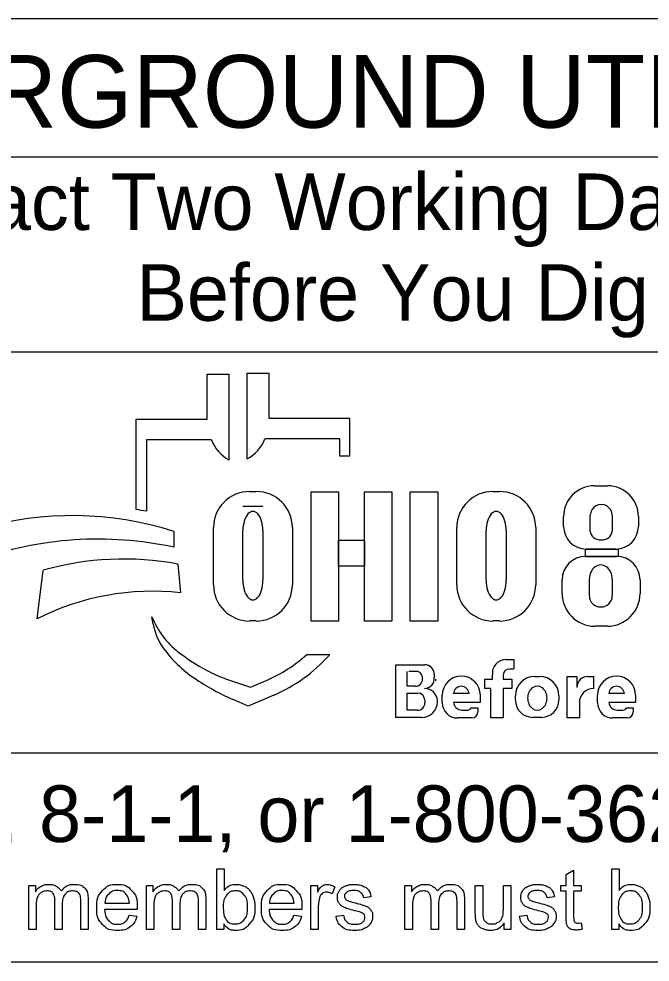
# Model space of a CAD drawing. Extents: x 0 to 34, y 0 to 22.
# Drawn here: x 26.673 to 28.237, y 9.069 to 11.406 of the extents above; entities that cross this region are included whole.
import ezdxf

# ---------------------------------------------------------------- set-up
doc = ezdxf.new("R2010")
doc.units = 0
doc.layers.add('SH_Data', color=7, linetype='Continuous')
doc.layers.add('SH_Text', color=7, linetype='Continuous')

msp = doc.modelspace()

# ---------------------------------------------------------------- linework, layer by layer
at = {"layer": 'SH_Data'}
for p, q in [((30.0333, 11.4064), (25.7833, 11.4064)), ((25.7833, 11.0648), (30.0333, 11.0648)), ((25.7833, 10.5814), (30.0333, 10.5814)), ((30.0333, 9.5868), (25.7833, 9.5868)), ((30.0333, 9.0689), (25.7833, 9.0689))]:
    msp.add_line(p, q, dxfattribs=at)
at = {"layer": 'SH_Text'}
for p, q in [((27.1394, 10.4144), (27.1394, 10.5259)), ((27.1394, 10.5259), (27.193, 10.5259)), ((27.193, 10.5259), (27.193, 10.3138)), ((27.2387, 10.3161), (27.2387, 10.5282)), ((27.2387, 10.5282), (27.2923, 10.5282)), ((27.2923, 10.5282), (27.2923, 10.4167)), ((26.9634, 10.1905), (26.9634, 10.4144)), ((26.9634, 10.4144), (27.1394, 10.4144)), ((27.2923, 10.4167), (27.4916, 10.4167)), ((27.4916, 10.4167), (27.4916, 10.3229)), ((26.9887, 10.363), (26.9887, 10.1861)), ((27.1498, 10.363), (26.9887, 10.363)), ((27.4683, 10.3653), (27.2819, 10.3653)), ((27.4683, 10.3229), (27.4683, 10.3653)), ((27.4916, 10.3229), (27.4683, 10.3229)), ((28.0989, 10.2492), (28.1317, 10.2492)), ((27.2444, 10.2352), (27.2609, 10.2352)), ((27.8474, 10.2352), (27.8639, 10.2352)), ((27.2776, 10.1982), (27.2278, 10.1982)), ((28.0226, 10.1486), (28.0226, 10.1729)), ((28.0888, 10.1372), (28.0888, 10.1765)), ((28.1429, 10.1765), (28.1429, 10.1372)), ((28.208, 10.1729), (28.208, 10.1486)), ((27.1549, 10.0037), (27.1549, 10.1457)), ((27.3504, 10.1457), (27.3504, 10.0037)), ((27.7579, 10.0037), (27.7579, 10.1457)), ((27.9534, 10.1457), (27.9534, 10.0037)), ((27.0567, 10.1358), (27.0567, 10.097)), ((27.2278, 10.0151), (27.2278, 10.1375)), ((27.2776, 10.1375), (27.2776, 10.0151)), ((27.8308, 10.0151), (27.8308, 10.1375)), ((27.8806, 10.1375), (27.8806, 10.0151)), ((28.152, 10.0926), (28.0786, 10.0926)), ((27.0667, 10.0552), (27.0729, 9.9843)), ((28.0768, 10.0743), (28.1541, 10.0743)), ((26.7179, 9.9197), (26.7326, 10.0398)), ((28.0189, 9.9824), (28.0189, 10.0164)), ((28.0864, 9.9764), (28.0864, 10.0173)), ((28.1433, 10.0173), (28.1433, 9.9764)), ((28.212, 10.0164), (28.212, 9.9824)), ((27.0056, 9.9068), (27.0025, 9.9247)), ((27.2609, 9.9143), (27.2444, 9.9143)), ((27.8639, 9.9143), (27.8474, 9.9143)), ((28.1311, 9.9014), (28.0999, 9.9014)), ((27.3859, 9.8309), (27.4433, 9.8309)), ((27.8797, 9.8187), (27.8992, 9.8187)), ((27.8992, 9.8187), (27.8992, 9.7957)), ((27.6072, 9.6751), (27.6072, 9.8059)), ((27.6072, 9.8059), (27.6783, 9.8059)), ((27.8992, 9.7952), (27.889, 9.7952)), ((27.6351, 9.7524), (27.6351, 9.7893)), ((27.6603, 9.7893), (27.6391, 9.7893)), ((27.7021, 9.7821), (27.7021, 9.7742)), ((27.8465, 9.7703), (27.8465, 9.7807)), ((27.8726, 9.7787), (27.8726, 9.7703)), ((27.951, 9.7769), (27.9631, 9.7769)), ((28.0312, 9.6739), (28.0312, 9.7766)), ((28.0312, 9.7766), (28.0558, 9.7766)), ((28.0558, 9.7766), (28.0558, 9.7498)), ((28.083, 9.7766), (28.0969, 9.7766)), ((28.0969, 9.7766), (28.0969, 9.747)), ((27.1874, 9.7705), (27.2469, 9.75)), ((27.2469, 9.75), (27.2879, 9.7678)), ((27.6545, 9.7524), (27.6351, 9.7524)), ((27.8271, 9.7473), (27.8271, 9.7703)), ((27.8271, 9.7703), (27.8465, 9.7703)), ((27.8726, 9.7703), (27.8941, 9.7703)), ((27.8941, 9.7703), (27.8941, 9.7473)), ((27.3041, 9.7305), (27.2408, 9.703)), ((27.6351, 9.693), (27.6351, 9.7358)), ((27.6351, 9.7358), (27.6607, 9.7358)), ((27.7217, 9.7119), (27.7217, 9.7303)), ((27.7883, 9.7343), (27.7498, 9.7343)), ((27.8162, 9.7303), (27.8162, 9.7127)), ((27.842, 9.7473), (27.8271, 9.7473)), ((27.842, 9.6739), (27.842, 9.7473)), ((27.8941, 9.7473), (27.8726, 9.7473)), ((27.8726, 9.7473), (27.8726, 9.6739)), ((27.9031, 9.7183), (27.9031, 9.729)), ((28.0109, 9.729), (28.0109, 9.7183)), ((28.1066, 9.7119), (28.1066, 9.7303)), ((28.1732, 9.7343), (28.1347, 9.7343)), ((28.2011, 9.7303), (28.2011, 9.7127)), ((27.2408, 9.703), (27.2035, 9.7195)), ((27.6788, 9.7177), (27.6788, 9.7114)), ((27.7101, 9.7148), (27.7101, 9.7145)), ((27.8162, 9.7127), (27.7498, 9.7127)), ((28.0617, 9.7121), (28.0617, 9.6739)), ((28.2011, 9.7127), (28.1347, 9.7127)), ((27.6604, 9.693), (27.6351, 9.693)), ((27.7707, 9.6934), (27.7849, 9.6934)), ((27.7934, 9.699), (27.8103, 9.699)), ((27.8103, 9.699), (27.8103, 9.6892)), ((28.1557, 9.6934), (28.1698, 9.6934)), ((28.1783, 9.699), (28.1952, 9.699)), ((28.1952, 9.699), (28.1952, 9.6892)), ((27.6708, 9.6751), (27.6072, 9.6751)), ((27.7951, 9.6739), (27.7597, 9.6739)), ((27.8726, 9.6739), (27.842, 9.6739)), ((27.9681, 9.6755), (27.9459, 9.6755)), ((28.0617, 9.6739), (28.0312, 9.6739)), ((28.18, 9.6739), (28.1446, 9.6739))]:
    msp.add_line(p, q, dxfattribs=at)
for points in [[(27.3968, 10.2342), (27.4648, 10.2342), (27.4648, 9.9142), (27.3968, 9.9142)], [(27.5289, 10.2342), (27.5969, 10.2342), (27.5969, 9.9142), (27.5289, 9.9142)], [(27.6423, 10.2342), (27.711, 10.2342), (27.711, 9.9142), (27.6423, 9.9142)], [(27.4648, 10.1143), (27.5289, 10.1143), (27.5289, 10.0503), (27.4648, 10.0503)], [(28.0765, 10.0926), (28.1582, 10.0926), (28.1582, 10.0742), (28.0765, 10.0742)]]:
    msp.add_lwpolyline(points, close=True, dxfattribs=at)
for points in [[(27.1802, 9.15), (27.1631, 9.15), (27.1631, 9.3002), (27.1815, 9.3002), (27.1815, 9.2467)], [(28.0291, 9.1819), (28.0291, 9.2446), (28.0155, 9.2446), (28.0155, 9.2589), (28.0291, 9.2589), (28.0291, 9.2858), (28.0475, 9.2969), (28.0475, 9.2589), (28.066, 9.2589), (28.066, 9.2446), (28.0475, 9.2446), (28.0475, 9.1808)], [(28.1592, 9.15), (28.1422, 9.15), (28.1422, 9.3002), (28.1606, 9.3002), (28.1606, 9.2467)], [(26.6971, 9.15), (26.6971, 9.2589), (26.7136, 9.2589), (26.7136, 9.2435)], [(26.9885, 9.15), (26.9885, 9.2589), (27.0049, 9.2589), (27.0049, 9.2435)], [(27.3962, 9.15), (27.3962, 9.2589), (27.4128, 9.2589), (27.4128, 9.2424)], [(27.6294, 9.15), (27.6294, 9.2589), (27.6459, 9.2589), (27.6459, 9.2435)], [(27.8038, 9.1915), (27.8038, 9.2589), (27.8222, 9.2589), (27.8222, 9.1985)], [(27.8735, 9.2006), (27.8735, 9.2589), (27.8919, 9.2589), (27.8919, 9.15), (27.8754, 9.15)], [(27.4553, 9.2554), (27.4488, 9.2383)], [(26.7802, 9.2132), (26.7802, 9.15), (26.7617, 9.15), (26.7617, 9.2207)], [(26.8446, 9.2247), (26.8446, 9.15), (26.8262, 9.15), (26.8262, 9.2185)], [(26.8857, 9.2148), (26.9465, 9.2148)], [(27.0715, 9.2132), (27.0715, 9.15), (27.0531, 9.15), (27.0531, 9.2207)], [(27.136, 9.2247), (27.136, 9.15), (27.1175, 9.15), (27.1175, 9.2185)], [(27.2937, 9.2148), (27.3545, 9.2148)], [(27.5452, 9.2307), (27.5272, 9.2283)], [(27.7125, 9.2132), (27.7125, 9.15), (27.6941, 9.15), (27.6941, 9.2207)], [(27.777, 9.2247), (27.777, 9.15), (27.7585, 9.15), (27.7585, 9.2185)], [(27.9998, 9.2307), (27.9817, 9.2283)], [(26.7155, 9.2064), (26.7155, 9.15), (26.6971, 9.15)], [(26.9658, 9.1997), (26.8847, 9.1997)], [(27.0069, 9.2064), (27.0069, 9.15), (26.9885, 9.15)], [(27.3738, 9.1997), (27.2927, 9.1997)], [(27.4147, 9.207), (27.4147, 9.15), (27.3962, 9.15)], [(27.6479, 9.2064), (27.6479, 9.15), (27.6294, 9.15)], [(26.9463, 9.1852), (26.9653, 9.1828)], [(27.1802, 9.1636), (27.1802, 9.15)], [(27.3543, 9.1852), (27.3733, 9.1828)], [(27.4588, 9.1825), (27.477, 9.1854)], [(27.8754, 9.15), (27.8754, 9.1661)], [(27.9134, 9.1825), (27.9316, 9.1854)], [(28.066, 9.1665), (28.0686, 9.1502)], [(28.1592, 9.1636), (28.1592, 9.15)]]:
    msp.add_lwpolyline(points, dxfattribs=at)
for centre, radius, start, end in [((27.2411, 10.3997), 0.0985, 201.9296, 240.7469), ((27.1906, 10.4021), 0.0985, 299.2531, 338.0704), ((28.0989, 10.1729), 0.0763, 90, 180), ((28.1317, 10.1729), 0.0763, 0, 90), ((27.2444, 10.1457), 0.0895, 90, 180), ((27.2609, 10.1457), 0.0895, 0, 90), ((27.8474, 10.1457), 0.0895, 90, 180), ((27.8639, 10.1457), 0.0895, 0, 90), ((26.8055, 9.3563), 0.8191, 72.1402, 106.3144), ((26.8353, 9.3815), 0.8191, 79.2074, 81.0007), ((28.0786, 10.1486), 0.056, 180, 270), ((28.152, 10.1486), 0.056, 270, 0), ((26.8686, 9.2252), 0.8919, 77.8238, 109.8274), ((26.9325, 9.3355), 0.7322, 79.44, 105.8467), ((28.0768, 10.0164), 0.0579, 90, 180), ((28.1541, 10.0164), 0.0579, 0, 90), ((27.0045, 9.3523), 0.6357, 83.8248, 116.8021), ((27.2444, 10.0037), 0.0895, 180, 270), ((27.2609, 10.0037), 0.0895, 270, 0), ((27.8474, 10.0037), 0.0895, 180, 270), ((27.8639, 10.0037), 0.0895, 270, 0), ((28.0999, 9.9824), 0.081, 180, 270), ((28.1311, 9.9824), 0.081, 270, 0), ((27.1899, 9.9968), 0.2008, 201.0457, 232.5314), ((27.1469, 9.9309), 0.1433, 189.6817, 216.0884), ((27.2805, 10.0283), 0.3088, 216.0884, 235.7167), ((27.3824, 10.248), 0.5173, 232.5314, 241.794), ((27.1445, 10.0983), 0.3602, 293.4582, 312.0712), ((27.1445, 10.0983), 0.401, 293.4582, 317.8286), ((27.8797, 9.7851), 0.0335, 90, 187.5187), ((27.6783, 9.7821), 0.0238, 0, 90), ((27.889, 9.7787), 0.0165, 90, 180), ((27.4471, 10.2726), 0.6044, 235.7167, 246.2325), ((27.2973, 10.0892), 0.3371, 241.794, 250.9821), ((27.6545, 9.7711), 0.0187, 270, 2.0582), ((27.6564, 9.7724), 0.0169, 357.8325, 90), ((27.6779, 9.7714), 0.0243, 270, 6.6529), ((27.769, 9.7303), 0.0473, 0, 180), ((27.951, 9.729), 0.0478, 90, 180), ((27.9631, 9.729), 0.0478, 0, 90), ((28.0826, 9.7498), 0.0269, 89.2449, 180), ((28.1539, 9.7303), 0.0473, 0, 180), ((27.6885, 9.7699), 0.0175, 347.4023, 0), ((27.769, 9.7333), 0.0193, 2.9632, 177.0368), ((28.1539, 9.7333), 0.0193, 2.9632, 177.0368), ((27.6607, 9.7177), 0.0181, 0, 90), ((27.678, 9.715), 0.0321, 4.0748, 90), ((28.0966, 9.7121), 0.0349, 89.6033, 180), ((27.6604, 9.7114), 0.0184, 270, 0), ((27.6708, 9.7145), 0.0393, 270, 0), ((27.6772, 9.7148), 0.033, 0, 11.7502), ((27.7597, 9.7119), 0.038, 180, 270), ((27.7707, 9.7144), 0.021, 184.827, 270), ((27.9459, 9.7183), 0.0428, 180, 270), ((27.9681, 9.7183), 0.0428, 270, 0), ((28.1446, 9.7119), 0.038, 180, 270), ((28.1557, 9.7144), 0.021, 184.827, 270), ((27.7849, 9.7028), 0.00938, 270, 335.9979), ((27.7951, 9.6892), 0.0152, 270, 0), ((28.1698, 9.7028), 0.00938, 270, 335.9979), ((28.18, 9.6892), 0.0152, 270, 0)]:
    msp.add_arc(centre, radius, start, end, dxfattribs=at)
for centre, major_axis, ratio, start_param, end_param in [((28.1159, 10.1765), (0.0271, 0), 0.969373, 0, 3.141593), ((27.2527, 10.1375), (0, 0.0484), 0.514403, 4.712389, 7.853982), ((27.8557, 10.1375), (0, 0.0484), 0.514403, 4.712389, 7.853982), ((28.1159, 10.1372), (0.0271, 0), 0.818453, 3.141593, 6.283185), ((28.1148, 10.0173), (0, 0.0358), 0.794529, 4.712389, 7.853982), ((27.2527, 10.0151), (0, 0.0484), 0.514403, 1.570796, 4.712389), ((27.8557, 10.0151), (0, 0.0484), 0.514403, 1.570796, 4.712389), ((28.1148, 9.9764), (0.0284, 0), 0.959837, 3.141593, 6.283185), ((27.9575, 9.7236), (0, 0.029), 0.832186, 4.712389, 7.853982), ((27.9575, 9.7236), (0, 0.0302), 0.797287, 1.570796, 4.712389)]:
    msp.add_ellipse(centre, major_axis=major_axis, ratio=ratio, start_param=start_param, end_param=end_param, dxfattribs=at)
for points in [[(26.7136, 9.2435), (26.7187, 9.2515), (26.7272, 9.2564), (26.7357, 9.2613), (26.7466, 9.2613), (26.7586, 9.2613), (26.7664, 9.2562), (26.7741, 9.2512), (26.7773, 9.2422), (26.7902, 9.2613), (26.8109, 9.2613), (26.8272, 9.2613), (26.8359, 9.2523), (26.8446, 9.2433), (26.8446, 9.2247)], [(26.9653, 9.1828), (26.9608, 9.1661), (26.9486, 9.1568), (26.9364, 9.1476), (26.9175, 9.1476), (26.8936, 9.1476), (26.8797, 9.1623), (26.8657, 9.177), (26.8657, 9.2035), (26.8657, 9.231), (26.8798, 9.2461), (26.8939, 9.2613), (26.9165, 9.2613), (26.9383, 9.2613), (26.9521, 9.2464), (26.9659, 9.2316), (26.9659, 9.2046), (26.9659, 9.203), (26.9658, 9.1997)], [(27.0049, 9.2435), (27.0101, 9.2515), (27.0186, 9.2564), (27.0271, 9.2613), (27.0379, 9.2613), (27.05, 9.2613), (27.0578, 9.2562), (27.0655, 9.2512), (27.0687, 9.2422), (27.0816, 9.2613), (27.1023, 9.2613), (27.1185, 9.2613), (27.1272, 9.2523), (27.136, 9.2433), (27.136, 9.2247)], [(27.1815, 9.2467), (27.1932, 9.2613), (27.2113, 9.2613), (27.2214, 9.2613), (27.2303, 9.2572), (27.2393, 9.2532), (27.2451, 9.2459), (27.2509, 9.2385), (27.2541, 9.2282), (27.2574, 9.2179), (27.2574, 9.2061), (27.2574, 9.1781), (27.2436, 9.1629), (27.2298, 9.1476), (27.2104, 9.1476), (27.1911, 9.1476), (27.1802, 9.1636)], [(27.3733, 9.1828), (27.3688, 9.1661), (27.3566, 9.1568), (27.3444, 9.1476), (27.3255, 9.1476), (27.3016, 9.1476), (27.2876, 9.1623), (27.2737, 9.177), (27.2737, 9.2035), (27.2737, 9.231), (27.2878, 9.2461), (27.3019, 9.2613), (27.3245, 9.2613), (27.3463, 9.2613), (27.3601, 9.2464), (27.3739, 9.2316), (27.3739, 9.2046), (27.3739, 9.203), (27.3738, 9.1997)], [(27.4128, 9.2424), (27.4192, 9.2539), (27.4245, 9.2576), (27.4299, 9.2613), (27.4364, 9.2613), (27.4457, 9.2613), (27.4553, 9.2554)], [(27.477, 9.1854), (27.4786, 9.1744), (27.4856, 9.1686), (27.4927, 9.1627), (27.5053, 9.1627), (27.518, 9.1627), (27.5242, 9.1679), (27.5304, 9.1731), (27.5304, 9.1801), (27.5304, 9.1863), (27.5249, 9.1899), (27.5211, 9.1924), (27.506, 9.1962), (27.4857, 9.2013), (27.4779, 9.205), (27.47, 9.2088), (27.466, 9.2154), (27.4619, 9.222), (27.4619, 9.2299), (27.4619, 9.2372), (27.4653, 9.2434), (27.4686, 9.2496), (27.4743, 9.2537), (27.4786, 9.2569), (27.4861, 9.2591), (27.4935, 9.2613), (27.502, 9.2613), (27.5149, 9.2613), (27.5246, 9.2576), (27.5343, 9.2539), (27.5389, 9.2476), (27.5435, 9.2413), (27.5452, 9.2307)], [(27.6459, 9.2435), (27.6511, 9.2515), (27.6596, 9.2564), (27.6681, 9.2613), (27.6789, 9.2613), (27.691, 9.2613), (27.6988, 9.2562), (27.7065, 9.2512), (27.7097, 9.2422), (27.7226, 9.2613), (27.7433, 9.2613), (27.7595, 9.2613), (27.7682, 9.2523), (27.777, 9.2433), (27.777, 9.2247)], [(27.9316, 9.1854), (27.9331, 9.1744), (27.9402, 9.1686), (27.9472, 9.1627), (27.9599, 9.1627), (27.9726, 9.1627), (27.9788, 9.1679), (27.9849, 9.1731), (27.9849, 9.1801), (27.9849, 9.1863), (27.9795, 9.1899), (27.9757, 9.1924), (27.9606, 9.1962), (27.9403, 9.2013), (27.9324, 9.205), (27.9246, 9.2088), (27.9205, 9.2154), (27.9165, 9.222), (27.9165, 9.2299), (27.9165, 9.2372), (27.9198, 9.2434), (27.9232, 9.2496), (27.9289, 9.2537), (27.9332, 9.2569), (27.9407, 9.2591), (27.9481, 9.2613), (27.9566, 9.2613), (27.9694, 9.2613), (27.9791, 9.2576), (27.9888, 9.2539), (27.9934, 9.2476), (27.9981, 9.2413), (27.9998, 9.2307)], [(28.1606, 9.2467), (28.1723, 9.2613), (28.1904, 9.2613), (28.2004, 9.2613), (28.2094, 9.2572), (28.2184, 9.2532), (28.2241, 9.2459), (28.2299, 9.2385), (28.2332, 9.2282), (28.2365, 9.2179), (28.2365, 9.2061), (28.2365, 9.1781), (28.2226, 9.1629), (28.2088, 9.1476), (28.1895, 9.1476), (28.1702, 9.1476), (28.1592, 9.1636)], [(26.7617, 9.2207), (26.7617, 9.233), (26.7572, 9.2391), (26.7527, 9.2452), (26.7425, 9.2452), (26.7347, 9.2452), (26.7281, 9.2411), (26.7214, 9.2371), (26.7185, 9.2292), (26.7155, 9.2213), (26.7155, 9.2064)], [(26.8262, 9.2185), (26.8262, 9.2296), (26.8244, 9.2344), (26.8226, 9.2393), (26.8179, 9.2423), (26.8132, 9.2452), (26.8068, 9.2452), (26.7953, 9.2452), (26.7877, 9.2376), (26.7802, 9.23), (26.7802, 9.2132)], [(26.9465, 9.2148), (26.9452, 9.2286), (26.9395, 9.2355), (26.9307, 9.2462), (26.9166, 9.2462), (26.9039, 9.2462), (26.8953, 9.2376), (26.8866, 9.2291), (26.8857, 9.2148)], [(27.0531, 9.2207), (27.0531, 9.233), (27.0486, 9.2391), (27.0441, 9.2452), (27.0338, 9.2452), (27.026, 9.2452), (27.0194, 9.2411), (27.0128, 9.2371), (27.0098, 9.2292), (27.0069, 9.2213), (27.0069, 9.2064)], [(27.1175, 9.2185), (27.1175, 9.2296), (27.1157, 9.2344), (27.114, 9.2393), (27.1092, 9.2423), (27.1045, 9.2452), (27.0982, 9.2452), (27.0867, 9.2452), (27.0791, 9.2376), (27.0715, 9.23), (27.0715, 9.2132)], [(27.1799, 9.2053), (27.1799, 9.1857), (27.1853, 9.177), (27.1939, 9.1627), (27.2088, 9.1627), (27.2208, 9.1627), (27.2296, 9.1732), (27.2384, 9.1837), (27.2384, 9.2045), (27.2384, 9.2259), (27.23, 9.236), (27.2215, 9.2462), (27.2096, 9.2462), (27.1975, 9.2462), (27.1887, 9.2357), (27.1799, 9.2251), (27.1799, 9.2053)], [(27.3545, 9.2148), (27.3532, 9.2286), (27.3475, 9.2355), (27.3387, 9.2462), (27.3246, 9.2462), (27.3119, 9.2462), (27.3033, 9.2376), (27.2946, 9.2291), (27.2937, 9.2148)], [(27.4488, 9.2383), (27.4421, 9.2423), (27.4354, 9.2423), (27.4294, 9.2423), (27.4246, 9.2386), (27.4198, 9.235), (27.4177, 9.2285), (27.4147, 9.2187), (27.4147, 9.207)], [(27.5272, 9.2283), (27.5259, 9.2367), (27.52, 9.2414), (27.5141, 9.2462), (27.5034, 9.2462), (27.4906, 9.2462), (27.4852, 9.2419), (27.4798, 9.2377), (27.4798, 9.2321), (27.4798, 9.2285), (27.482, 9.2256), (27.4843, 9.2227), (27.4891, 9.2207), (27.4919, 9.2197), (27.5054, 9.216), (27.525, 9.2108), (27.5328, 9.2074), (27.5405, 9.2041), (27.5449, 9.1978), (27.5494, 9.1914), (27.5494, 9.182), (27.5494, 9.1728), (27.544, 9.1647), (27.5386, 9.1565), (27.5284, 9.1521), (27.5183, 9.1476), (27.5054, 9.1476), (27.4842, 9.1476), (27.473, 9.1564), (27.4619, 9.1652), (27.4588, 9.1825)], [(27.6941, 9.2207), (27.6941, 9.233), (27.6896, 9.2391), (27.6851, 9.2452), (27.6748, 9.2452), (27.667, 9.2452), (27.6604, 9.2411), (27.6538, 9.2371), (27.6508, 9.2292), (27.6479, 9.2213), (27.6479, 9.2064)], [(27.7585, 9.2185), (27.7585, 9.2296), (27.7567, 9.2344), (27.755, 9.2393), (27.7502, 9.2423), (27.7455, 9.2452), (27.7392, 9.2452), (27.7277, 9.2452), (27.7201, 9.2376), (27.7125, 9.23), (27.7125, 9.2132)], [(27.9817, 9.2283), (27.9805, 9.2367), (27.9746, 9.2414), (27.9687, 9.2462), (27.9579, 9.2462), (27.9452, 9.2462), (27.9398, 9.2419), (27.9343, 9.2377), (27.9343, 9.2321), (27.9343, 9.2285), (27.9366, 9.2256), (27.9389, 9.2227), (27.9437, 9.2207), (27.9464, 9.2197), (27.96, 9.216), (27.9796, 9.2108), (27.9873, 9.2074), (27.9951, 9.2041), (27.9995, 9.1978), (28.0039, 9.1914), (28.0039, 9.182), (28.0039, 9.1728), (27.9985, 9.1647), (27.9932, 9.1565), (27.983, 9.1521), (27.9728, 9.1476), (27.96, 9.1476), (27.9388, 9.1476), (27.9276, 9.1564), (27.9165, 9.1652), (27.9134, 9.1825)], [(28.159, 9.2053), (28.159, 9.1857), (28.1643, 9.177), (28.173, 9.1627), (28.1878, 9.1627), (28.1999, 9.1627), (28.2087, 9.1732), (28.2175, 9.1837), (28.2175, 9.2045), (28.2175, 9.2259), (28.209, 9.236), (28.2006, 9.2462), (28.1886, 9.2462), (28.1766, 9.2462), (28.1678, 9.2357), (28.159, 9.2251), (28.159, 9.2053)], [(26.8847, 9.1997), (26.8857, 9.1818), (26.8948, 9.1723), (26.9039, 9.1627), (26.9176, 9.1627), (26.9277, 9.1627), (26.9349, 9.1681), (26.9421, 9.1734), (26.9463, 9.1852)], [(27.2927, 9.1997), (27.2937, 9.1818), (27.3028, 9.1723), (27.3119, 9.1627), (27.3256, 9.1627), (27.3357, 9.1627), (27.3429, 9.1681), (27.3501, 9.1734), (27.3543, 9.1852)], [(27.8754, 9.1661), (27.8627, 9.1476), (27.8409, 9.1476), (27.8313, 9.1476), (27.823, 9.1513), (27.8146, 9.155), (27.8106, 9.1606), (27.8065, 9.1662), (27.8049, 9.1743), (27.8038, 9.1797), (27.8038, 9.1915)], [(27.8222, 9.1985), (27.8222, 9.1841), (27.8233, 9.1791), (27.8251, 9.1718), (27.8307, 9.1677), (27.8363, 9.1635), (27.8446, 9.1635), (27.8529, 9.1635), (27.8602, 9.1678), (27.8674, 9.172), (27.8704, 9.1793), (27.8735, 9.1867), (27.8735, 9.2006)], [(28.0686, 9.1502), (28.0608, 9.1485), (28.0547, 9.1485), (28.0447, 9.1485), (28.0391, 9.1517), (28.0336, 9.1549), (28.0314, 9.1601), (28.0291, 9.1653), (28.0291, 9.1819)], [(28.0475, 9.1808), (28.0475, 9.1729), (28.0485, 9.1706), (28.0495, 9.1684), (28.0517, 9.167), (28.0538, 9.1657), (28.0579, 9.1657), (28.061, 9.1657), (28.066, 9.1665)]]:
    msp.add_open_spline(points, degree=3, dxfattribs=at)

# ---------------------------------------------------------------- texts
for s, height, p in [('UNDERGROUND UTILITIES', 0.18, (25.9115, 11.1367)), ('Contact Two Working Days', 0.14, (26.203, 10.8832)), ('Before You Dig', 0.14, (26.9642, 10.6582)), ('OHIO811, 8-1-1, or 1-800-362-2764', 0.14, (25.8278, 9.3667))]:
    msp.add_text(s, height=height, dxfattribs=at).set_placement(p)

doc.saveas('drawing.dxf')
